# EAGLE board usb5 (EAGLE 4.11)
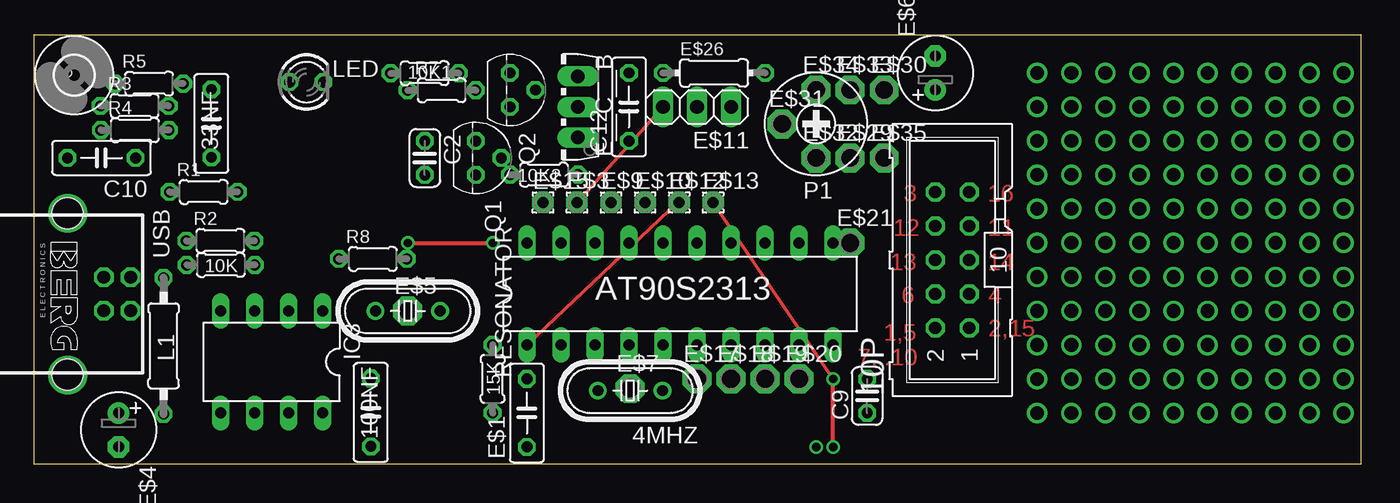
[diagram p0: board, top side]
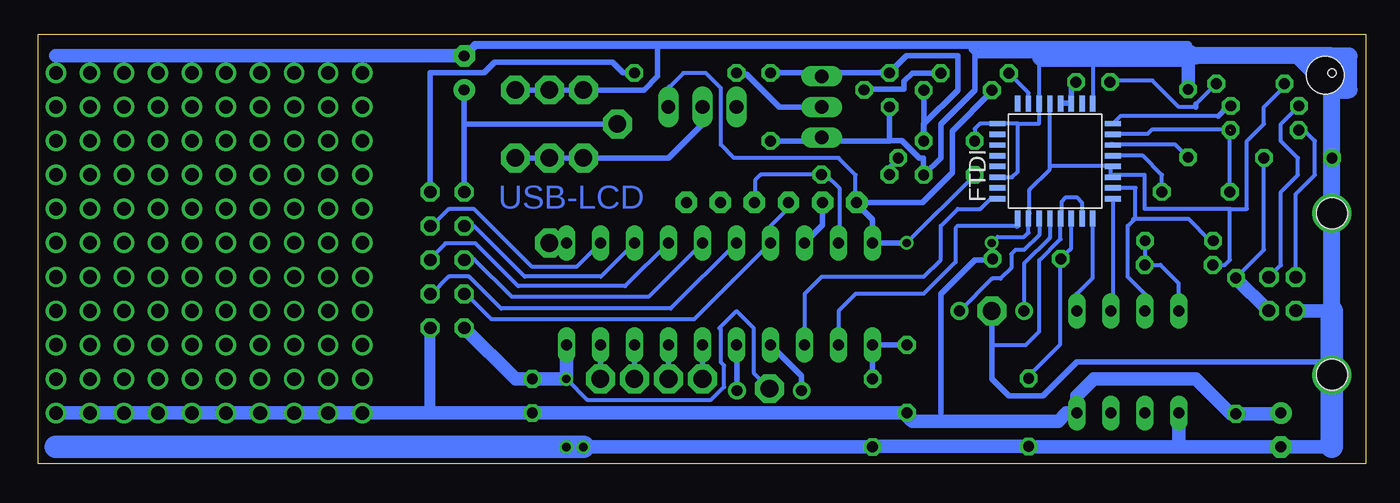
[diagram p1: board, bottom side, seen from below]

Size 99.13 x 32.09 mm. Coordinates in mm from the lower left corner, seen from the top.
Outline: 99.13,32.09 99.13,0 0,0 0,32.08
Outline: 0,32.09 0,32.08
Outline: 0,32.08 99.12,32.08
Copper layers (1*16): Top 0.035mm / dielectric 1.5mm / Bottom 0.035mm
Design rules "default": minimum track width 10mil, minimum drill 24mil, track to track 8mil, track to pad 8mil, pad to pad 8mil, via to via 8mil, smd to smd 8mil, copper to edge 40mil, drill to drill 8mil, minimum pad ring 10mil, minimum via ring 8mil, stop-mask expansion 4mil, vias tented up to drill 0mil, thermal gap 10mil
Holes 0.61 mm at 2.54,29.21

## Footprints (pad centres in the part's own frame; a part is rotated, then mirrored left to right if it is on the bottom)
HC49/S = drill 0.813 round: 1 -2.413,0; 2 2.413,0
0204/5 = drill 0.813 octagon: 1 -2.54,0; 2 2.54,0
ML10 = drill 0.914 octagon: 1 -5.08,-1.27; 2 -5.08,1.27; 3 -2.54,-1.27; 4 -2.54,1.27; 5 0,-1.27; 6 0,1.27; 7 2.54,-1.27; 8 2.54,1.27; 9 5.08,-1.27; 10 5.08,1.27
C050-025X075 = drill 0.813 octagon: 1 -2.54,0; 2 2.54,0
DIL20 = drill 0.813 long: 1 -11.43,-3.81; 2 -8.89,-3.81; 3 -6.35,-3.81; 4 -3.81,-3.81; 5 -1.27,-3.81; 6 1.27,-3.81; 7 3.81,-3.81; 8 6.35,-3.81; 9 8.89,-3.81; 10 11.43,-3.81; 11 11.43,3.81; 12 8.89,3.81; 13 6.35,3.81; 14 3.81,3.81; 15 1.27,3.81; 16 -1.27,3.81; 17 -3.81,3.81; 18 -6.35,3.81; 19 -8.89,3.81; 20 -11.43,3.81
C025-024X044 = drill 0.813 octagon: 1 -1.27,0; 2 1.27,0
2,8 = hole 2.8: 0,0
1,6/0,8 = drill 0.813 pad 1.6 octagon: 1 0,0
E2,5-6 = drill 0.813 pad 1.6 round: + -1.27,0 | drill 0.813 pad 1.6 octagon: - 1.27,0
P1-13 = drill 1.321 pad 2.159 octagon: 1 0,0
1X03 = drill 1.016 long: 1 -2.54,0; 2 0,0; 3 2.54,0
0204/7 = drill 0.813 octagon: 1 -3.81,0; 2 3.81,0
TO126AV = drill 1.016 long: B 2.286,-1.27; C 0,-1.27; E -2.286,-1.27
LQFP32 = smd 0.4 x 1.2: 1 -2.8,-4.3; 2 -2,-4.3; 3 -1.2,-4.3; 4 -0.4,-4.3; 5 0.4,-4.3; 6 1.2,-4.3; 7 2,-4.3; 8 2.8,-4.3; 17 2.8,4.3; 18 2,4.3; 19 1.2,4.3; 20 0.4,4.3; 21 -0.4,4.3; 22 -1.2,4.3; 23 -2,4.3; 24 -2.8,4.3 | smd 1.2 x 0.4: 9 4.3,-2.8; 10 4.3,-2; 11 4.3,-1.2; 12 4.3,-0.4; 13 4.3,0.4; 14 4.3,1.2; 15 4.3,2; 16 4.3,2.8; 25 -4.3,2.8; 26 -4.3,2; 27 -4.3,1.2; 28 -4.3,0.4; 29 -4.3,-0.4; 30 -4.3,-1.2; 31 -4.3,-2; 32 -4.3,-2.8
DIL08 = drill 0.813 long: 1 -3.81,-3.81; 2 -1.27,-3.81; 3 1.27,-3.81; 4 3.81,-3.81; 5 3.81,3.81; 6 1.27,3.81; 7 -1.27,3.81; 8 -3.81,3.81
0207/10 = drill 0.813 octagon: 1 -5.08,0; 2 5.08,0
LED3MM = drill 0.813 octagon: A -1.27,0; K 1.27,0
RTRIM3339P = drill 0.61 round: 1 -2.54,0; 2 0,-2.54; 3 2.54,0
TO92 = drill 0.813 octagon: 1 1.27,0; 2 0,1.905; 3 -1.27,0
PN61729 = drill 0.95 octagon: 1 1.25,4.71; 2 -1.25,4.71; 3 -1.25,2.71; 4 1.25,2.71 | hole 2.3: -6.02,0; 6.02,0

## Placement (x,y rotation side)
4MHZ  4Mhz  [HC49/S]  44.54,5.48 180 top
10K  15k  [0204/5]  13.98,14.87 180 top
10K1  10k  [0204/5]  29.2,29.19 0 top
10K2  10k  [0204/5]  38.11,21.61 180 top
10P  LCD  [ML10]  68.58,15.24 90 top
15K  15k  [0204/5]  34.27,6.36 270 top
33NF  [C050-025X075]  13.28,25.44 90 top
100NF  [C050-025X075]  25.18,3.85 90 top
AT90S2313  AT90S2313  [DIL20]  48.26,12.7 0 top
C2  100nf  [C025-024X044]  29.21,22.86 270 top
C9  100nf  [C025-024X044]  62.23,5.08 90 top
C10  10nF  [C050-025X075]  5.08,22.86 180 top
C12  100nF  [C050-025X075]  44.45,26.67 90 top
E$1  100nF  [C050-025X075]  36.83,3.81 90 top
E$2  [2,8]  3.04,29.04 0 top
E$3  [1,6/0,8]  40.57,19.53 0 top
E$4  10uf  [E2,5-6]  6.35,2.54 270 top
E$5  [P1-13]  27.94,11.43 0 top
E$6  10uF  [E2,5-6]  67.31,29.21 90 top
E$7  [P1-13]  44.53,5.63 0 top
E$9  [1,6/0,8]  43.11,19.53 0 top
E$10  [1,6/0,8]  45.65,19.53 0 top
E$11  [1X03]  49.53,26.67 180 top
E$12  [1,6/0,8]  48.19,19.53 0 top
E$13  [1,6/0,8]  50.73,19.53 0 top
E$15  [1,6/0,8]  38.03,19.53 0 top
E$17  [P1-13]  49.53,6.35 0 top
E$18  [P1-13]  52.07,6.35 0 top
E$19  [P1-13]  54.61,6.35 0 top
E$20  [P1-13]  57.15,6.35 0 top
E$21  [P1-13]  60.96,16.51 0 top
E$26  rx  [0204/7]  50.8,29.21 0 top
E$29  [P1-13]  60.96,22.86 0 top
E$30  [P1-13]  63.5,27.94 0 top
E$31  [P1-13]  55.88,25.4 0 top
E$32  [P1-13]  58.42,22.86 0 top
E$33  [P1-13]  60.96,27.94 0 top
E$34  [P1-13]  58.42,27.94 0 top
E$35  [P1-13]  63.5,22.86 0 top
E__C__B  BD139  [TO126AV]  39.37,26.67 90 top
FTDI  FT232BM  [LQFP32]  23.2,22.62 90 bottom
IC3  93C48  [DIL08]  17.78,7.62 180 top
L1  [0207/10]  9.71,8.82 270 top
LED  [LED3MM]  20.38,28.53 0 top
P1  10K  [RTRIM3339P]  58.42,25.4 270 top
Q1  [TO92]  33.02,22.86 270 top
Q2  BC547  [TO92]  35.56,27.94 270 top
R1  1k5  [0204/5]  12.7,20.32 0 top
R2  2k2  [0204/5]  13.95,16.67 0 top
R3  27  [0204/5]  7.55,26.75 0 top
R4  27  [0204/5]  7.57,24.94 0 top
R5  220  [0204/5]  8.63,28.41 0 top
R7  1k  [0204/5]  30.47,27.92 0 top
R8  470  [0204/5]  25.33,15.32 0 top
RESONATOR  6Mhz  [HC49/S]  27.94,11.43 180 top
USB  [PN61729]  2.54,12.7 270 top

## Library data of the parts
4MHZ RESONATOR = crystal
10K 10K1 10K2 15K 33NF 100NF C2 C9 C10 C12 E$1 E$4 E$6 E$26 L1 P1 R1-R5 R7 R8 = rcl
10P = con-harting-ml
AT90S2313 = atmel
E$2 = holes
E$3 E$9 E$10 E$12 E$13 E$15 = wirepad
E$5 E$7 E$17-E$21 E$29-E$35 = testpad
E$11 = pinhead
E__C__B = transistor-power
FTDI = ftdi_FT2XXBM
IC3 = ic-package
LED = led
Q1 Q2 = transistor
USB = con-berg

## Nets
GND: 10P.2 33NF.2 100NF.1 AT90S2313.10 C9.2 E$1.1 E$4.- E$5.1 E$6.- E$7.1 E$13.1 E$30.1 E$33.1 FTDI.9 FTDI.29 FTDI.31 IC3.5 P1.1 USB.4
S$1: R3.1 USB.2
S$3: FTDI.28 RESONATOR.2
S$6: 100NF.2 FTDI.30 R8.1
S$7: R4.1 USB.3
S$8: FTDI.8 R3.2
S$9: FTDI.7 R1.1 R4.2
S$11: 10K.1 IC3.4 R2.2
S$12: FTDI.27
S$13: FTDI.1 IC3.2
S$14: FTDI.2 IC3.3 R2.1
S$15: FTDI.5 R1.2
S$16: 33NF.1 FTDI.6
S$17: LED.A R5.2
S$18: 15K.1 AT90S2313.1 E$1.2 E$12.1
S$19: RESONATOR.1
S$20: C10.1 L1.1 USB.1
S$21: C2.1 FTDI.17
S$22: AT90S2313.3 FTDI.24
S$23: E$26.1 E__C__B.C
S$24: AT90S2313.2 FTDI.25
S$25: 4MHZ.2 AT90S2313.4
S$26: 4MHZ.1 AT90S2313.5
S$27: AT90S2313.6 E$17.1
S$28: AT90S2313.7 E$18.1
S$29: AT90S2313.8 E$19.1
S$30: AT90S2313.9 E$20.1
S$31: AT90S2313.11 E$21.1
S$32: 10K1.1 FTDI.15
S$33: C12.2 E__C__B.B Q1.3 Q2.3 R7.2
S$34: 10K1.2 Q2.2
S$36: FTDI.14 FTDI.22
S$37: 10K2.1 AT90S2313.19 E$10.1
S$38: 10K2.2 Q1.2
S$39: 10P.9 E$26.2
S$40: AT90S2313.18 E$3.1 E$11.3
S$41: E$11.2 E$29.1 E$35.1 P1.3
S$42: 10P.10 E$6.+ P1.2
S$43: 10P.7 AT90S2313.12
S$44: 10P.8 AT90S2313.13
S$45: 10P.5 AT90S2313.14
S$46: 10P.6 AT90S2313.15
S$47: 10P.3 AT90S2313.16
S$48: 10P.4 AT90S2313.17 E$9.1
S$49: C12.1 E__C__B.E Q1.1 Q2.1
S$150: FTDI.11 FTDI.12 LED.K
S$153: AT90S2313.20 C2.2 E$11.1 E$15.1 FTDI.13 FTDI.26 R7.1 R8.2
S$154: 10K.2 FTDI.3 FTDI.4 R5.1
S$158: FTDI.32 IC3.1
VCC: 10P.1 15K.2 E$4.+ IC3.8 L1.2

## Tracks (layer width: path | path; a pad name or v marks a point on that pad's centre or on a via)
GND  (via drill 0.61)
  Top 0.254: v59.69,6.35 E$13.1
  Top 0.305: v59.69,1.27 v59.69,6.35
  Bottom 0.254: 23.92,30.48 23.92,30.16 2.56,30.16 2.54,11.43 USB.4
  Bottom 0.305: E$7.1 45.72,6.82 45.72,10.16 46.99,11.43 48.26,10.16 48.16,10.06 48.16,7.6 47.92,7.36 47.92,5.76 48.88,4.8 58.14,4.8 v59.69,6.35 | 20.4,30.4 FTDI.9 | FTDI.31 21.2,19.52 21.6,19.92 22.4,19.92 22.72,19.6 22.72,18.24 FTDI.29 22.8,16.8 24.4,15.2 24.4,9.89 25.4,8.89 27.94,8.89
  Bottom 0.406: P1.1 E$33.1 E$30.1 53.9,27.94 52.88,28.96 52.88,31.28 | 20.32,30.48 20.4,30.4 | USB.4 5.23,11.43 2.54,11.43 | E$5.1 27.94,8.89 27.94,6.35 26.67,5.08 24.13,5.08 21.59,7.62 2.54,7.62
  Bottom 0.425: 100NF.1 25.36,1.31 25.4,1.27
  Bottom 0.61: E$6.- 66.51,31.28 52.88,31.28 13.28,31.28 13.28,28 | 13.28,28 13.2,28 | 33NF.2 13.28,28
  Bottom 1: E$1.1 v58.42,1.27
  Bottom 1.016: E$6.- 97.79,30.48 | 10P.2 63.5,6.35 C9.2 v59.69,6.35 AT90S2313.10 | 13.28,30.48 33NF.2 | E$1.1 36.83,1.31 25.4,1.31 | 25.4,1.31 100NF.1 | 25.4,1.31 25.4,1.27 13.97,1.27 | 13.97,1.27 IC3.5 | 13.97,1.27 E$4.- 2.54,1.27 | 2.54,11.43 5.08,11.43
  Bottom 1.27: 5.08,30.48 12.7,30.48 | 3.81,29.21 5.08,30.48 | 2.54,30.48 5.08,30.48 | 2.54,30.48 1.27,30.48 1.27,27.94 2.54,27.94 | 2.54,30.48 3.81,29.21 | 2.54,27.94 2.54,30.48 | 2.54,27.94 3.81,29.21 | 2.54,11.43 2.54,27.94
  Bottom 1.676: 97.79,1.27 v59.69,1.27 v58.42,1.27 | 13.28,30.48 20.32,30.48 23.92,30.48 24.13,30.48 | 2.54,1.27 2.54,7.62 2.54,11.43
S$1
  Bottom 0.305: USB.2 6.35,14.85 6.35,20.32 5.08,21.59 5.08,22.86 6.35,24.13 6.35,25.4 5.08,26.67
  Bottom 0.406: 5.08,26.67 5.08,26.68 R3.1
S$2  (via drill 0.61)
  other vias: 25.2,1.28
S$3
  Bottom 0.305: FTDI.28 23.6,16.88 25.52,14.96 25.52,11.52 25.6,11.44 25.59,11.43 RESONATOR.2
S$4  (via drill 1.93)
  other vias: 2.56,6.64
S$5  (via drill 1.93)
  other vias: 2.56,18.72
S$6
  Bottom 0.305: 22.8,15.3 arc-45 R8.1 arc45 22.8,15.3 | 22.8,15.3 22.86,15.24 | FTDI.30 22,16.23 arc45 22.09,16.01 22.86,15.24 | 22.86,15.24 22.86,8.89 25.36,6.39 | 25.4,6.35 25.36,6.39 | 25.36,6.39 100NF.2
S$7
  Bottom 0.305: USB.3 5.25,20.15 3.81,21.59 3.81,24.13 5.08,25.4
  Bottom 0.406: 5.08,25.4 R4.1
S$8
  Bottom 0.305: FTDI.8 18.32,26 11.04,26
  Bottom 0.406: 10.06,26.72 10,26.72 | R3.2 10.06,26.72 | 11.04,26 10.32,26.72 10.06,26.72
S$9  (1 unrouted)
  Bottom 0.305: R1.1 10.16,24.96 16,24.96 16.32,24.64 18.92,24.64
  Bottom 0.406: 19.04,24.64 18.92,24.64 FTDI.7
S$11
  Bottom 0.305: 16.52,14.84 16.56,14.8 | 16.52,14.84 10K.1 15.35,14.87 14,13.52 14,11.46 IC3.4 | R2.2 16.49,14.87 16.52,14.84
S$12
  Bottom 0.305: FTDI.27 24.4,18.16
S$13
  Bottom 0.305: FTDI.1 18.9,11.58 IC3.2
S$14
  Bottom 0.305: 17.2,18.32 17.36,18.32 17.36,18.2 17.78,17.78 17.78,13.97 16.51,12.7 IC3.3 | 17.2,18.32 13.28,18.32 11.68,16.72 11.36,16.72 R2.1 | FTDI.2 17.2,20.62 17.2,18.32
S$15
  Bottom 0.305: FTDI.5 16.67,23.02 15.24,21.59 R1.2
S$16
  Bottom 0.305: 33NF.1 14.22,23.84 18.92,23.84
  Bottom 0.406: 19.04,23.84 18.92,23.84 FTDI.6
S$17
  Bottom 0.305: R5.2 12.7,26.88 | 12.7,26.67 13.97,26.67 15.94,28.64 19.04,28.64
  Bottom 0.406: 12.7,26.88 12.7,26.67 | 19.04,28.64 19.04,28.6 LED.A
S$18
  Top 0.254: E$12.1 48.16,19.6 AT90S2313.1
  Bottom 0.406: 15K.1 AT90S2313.1 E$1.2
S$19
  Bottom 0.305: 24.4,18 24.4,17.12 25.52,16 26.16,16 26.48,15.68 26.48,14.64 27.28,13.84 27.92,13.84 30.33,11.43 RESONATOR.1
S$20
  Bottom 0.305: L1.1 7.62,15.99 C10.1
  Bottom 1.016: L1.1 9.71,13.87 7.29,11.45 USB.1
S$21
  Bottom 0.305: FTDI.17 28.82,25.42 29.2,25.04 29.2,24 29.21,24.01 C2.1
S$22
  Bottom 0.305: AT90S2313.3 41.91,12.7 40.64,13.97 33.02,13.97 31.75,15.24 31.75,17.78 30.48,19.05 28.79,19.05 28,19.84 27.98,19.82 FTDI.24
S$23
  Bottom 0.406: E__C__B.C 43.79,26.67 46.24,29.12 46.72,29.12 46.81,29.21 E$26.1
S$24
  Bottom 0.305: AT90S2313.2 39.37,11.43 38.1,12.7 33.02,12.7 30.64,15.08 30.64,17.62 30.48,17.78 26.06,17.78 | FTDI.25 26,17.84
  Bottom 0.406: 26,17.84 26.06,17.78
S$25
  Bottom 0.406: 4MHZ.2 42.13,6.57 AT90S2313.4
S$26
  Bottom 0.406: 4MHZ.1 46.95,8.85 AT90S2313.5
S$27
  Bottom 0.406: E$17.1 AT90S2313.6
S$28
  Bottom 0.406: E$18.1 AT90S2313.7
S$29
  Bottom 0.406: E$19.1 AT90S2313.8
S$30
  Bottom 0.406: E$20.1 AT90S2313.9
S$31
  Bottom 0.305: AT90S2313.11 E$21.1
S$32
  Bottom 0.305: 10K1.1 25.2,27.73 FTDI.15
S$33
  Bottom 0.406: 40.64,29.21 C12.2 | R7.2 Q1.3
  Bottom 0.425: E__C__B.B 40.64,29.21 Q2.3 34.29,30.48 30.48,30.48 30.48,27.94 33.02,25.4 Q1.3
S$34
  Bottom 0.425: 10K1.2 33.87,29.19 34.48,28.58 34.48,28 37.44,28 37.44,27.96 Q2.2
S$35  (via drill 1.02)
  other vias: 85.09,26.67
S$36
  Bottom 0.305: 24.4,29.84 FTDI.14 24.4,25.44 26,25.44 | 26,25.44 27.36,25.44 | 26,25.44 26,21.84 26.42,21.42 FTDI.22
S$37
  Bottom 0.305: 39.28,16.6 39.28,20.56 40.31,21.59 | 10K2.1 45.19,21.61 45.6,21.2 45.6,19.52
  Bottom 0.406: AT90S2313.19 39.28,16.6 | 10K2.1 40.64,21.59 40.31,21.59 | 45.6,19.52 45.61,19.53 E$10.1
S$38
  Bottom 0.406: Q1.2 34.92,22.84 34.88,22.8 35.57,22.11 10K2.2
S$39
  Bottom 0.406: E$26.2 55.45,29.21 56.24,30 65.04,30 65.83,29.21 69.85,29.21 10P.9
S$40
  Top 0.254: E$3.1 E$11.3
  Bottom 0.406: E$3.1 40.56,19.6 | E$3.1 | AT90S2313.18 40.56,17.86 E$3.1
S$41
  Bottom 0.406: E$11.2 49.53,25.4 52.07,22.86 P1.3 E$29.1 E$35.1
S$42
  Bottom 0.406: P1.2 67.31,25.4 E$6.+ 10P.10
S$43
  Bottom 0.305: AT90S2313.12 58.94,14.72 62.24,14.72 66.56,19.04 68.48,19.04 69.74,17.78 10P.7
S$44
  Bottom 0.305: AT90S2313.13 57.12,14 62.8,14 66.56,17.76 67.29,17.76 10P.8
S$45
  Bottom 0.305: AT90S2313.14 55.3,13.28 63.28,13.28 66.48,16.48 68.72,16.48 69.84,15.36 10P.5 | 10P.5 69.84,15.12 | 10P.5
S$46
  Bottom 0.305: AT90S2313.15 53.56,12.48 63.76,12.48 66.56,15.28 67.35,15.28 | 67.35,15.28 67.36,15.28 | 67.35,15.28 10P.6
S$47
  Bottom 0.305: AT90S2313.16 51.9,11.6 64.56,11.6 66.96,14 68.48,14 69.84,12.64 69.91,12.64 | 69.91,12.64 69.92,12.64 | 69.91,12.64 10P.3
S$48
  Bottom 0.305: 43.12,19.11 44.45,17.78 AT90S2313.17 50.16,10.8 65.28,10.8 67.2,12.72 67.29,12.72 10P.4
  Bottom 0.406: E$9.1 43.12,19.11
S$49
  Bottom 0.406: 35.6,24.13 35.6,24.16 34.64,24.16 33.34,22.86 33.02,22.86 Q1.1
  Bottom 0.425: 40.39,24.13 C12.1 | 40.39,24.13 E__C__B.E | Q2.1 35.56,24.13 35.6,24.13 40.39,24.13 | 25.2,30.96 28.72,30.96 29.2,30.48 29.21,30.48 29.21,27.94 31.75,25.4 31.75,22.86 Q1.1
S$50  (via drill 1.02)
  other vias: 74.93,29.21
S$51  (via drill 1.02)
  other vias: 77.47,29.21
S$52  (via drill 1.02)
  other vias: 80.01,29.21
S$53  (via drill 1.02)
  other vias: 82.55,29.21
S$54  (via drill 1.02)
  other vias: 85.09,29.21
S$55  (via drill 1.02)
  other vias: 87.63,29.21
S$56  (via drill 1.02)
  other vias: 90.17,29.21
S$57  (via drill 1.02)
  other vias: 92.71,29.21
S$58  (via drill 1.02)
  other vias: 95.25,29.21
S$59  (via drill 1.02)
  other vias: 97.79,29.21
S$60  (via drill 1.02)
  other vias: 74.93,26.67
S$61  (via drill 1.02)
  other vias: 77.47,26.67
S$62  (via drill 1.02)
  other vias: 80.01,26.67
S$63  (via drill 1.02)
  other vias: 82.55,26.67
S$64  (via drill 1.02)
  other vias: 87.63,26.67
S$65  (via drill 1.02)
  other vias: 90.17,26.67
S$66  (via drill 1.02)
  other vias: 92.71,26.67
S$67  (via drill 1.02)
  other vias: 95.25,26.67
S$68  (via drill 1.02)
  other vias: 97.79,26.67
S$69  (via drill 1.02)
  other vias: 97.79,24.13
S$70  (via drill 1.02)
  other vias: 97.79,21.59
S$71  (via drill 1.02)
  other vias: 97.79,19.05
S$72  (via drill 1.02)
  other vias: 97.79,16.51
S$73  (via drill 1.02)
  other vias: 97.79,13.97
S$74  (via drill 1.02)
  other vias: 97.79,11.43
S$75  (via drill 1.02)
  other vias: 97.79,8.89
S$76  (via drill 1.02)
  other vias: 97.79,6.35
S$77  (via drill 1.02)
  other vias: 95.25,6.35
S$78  (via drill 1.02)
  other vias: 92.71,6.35
S$79  (via drill 1.02)
  other vias: 90.17,6.35
S$80  (via drill 1.02)
  other vias: 74.93,24.13
S$81  (via drill 1.02)
  other vias: 74.93,21.59
S$82  (via drill 1.02)
  other vias: 74.93,19.05
S$83  (via drill 1.02)
  other vias: 74.93,16.51
S$84  (via drill 1.02)
  other vias: 74.93,13.97
S$85  (via drill 1.02)
  other vias: 77.47,24.13
S$86  (via drill 1.02)
  other vias: 80.01,21.59
S$87  (via drill 1.02)
  other vias: 77.47,21.59
S$88  (via drill 1.02)
  other vias: 80.01,24.13
S$89  (via drill 1.02)
  other vias: 82.55,24.13
S$90  (via drill 1.02)
  other vias: 82.55,21.59
S$91  (via drill 1.02)
  other vias: 85.09,21.59
S$92  (via drill 1.02)
  other vias: 85.09,24.13
S$93  (via drill 1.02)
  other vias: 87.63,24.13
S$94  (via drill 1.02)
  other vias: 90.17,24.13
S$95  (via drill 1.02)
  other vias: 92.71,24.13
S$96  (via drill 1.02)
  other vias: 95.25,24.13
S$97  (via drill 1.02)
  other vias: 95.25,21.59
S$98  (via drill 1.02)
  other vias: 92.71,21.59
S$99  (via drill 1.02)
  other vias: 90.17,21.59
S$100  (via drill 1.02)
  other vias: 87.63,21.59
S$101  (via drill 1.02)
  other vias: 85.09,19.05
S$102  (via drill 1.02)
  other vias: 82.55,19.05
S$103  (via drill 1.02)
  other vias: 80.01,19.05
S$104  (via drill 1.02)
  other vias: 77.47,19.05
S$105  (via drill 1.02)
  other vias: 77.47,16.51
S$106  (via drill 1.02)
  other vias: 80.01,16.51
S$107  (via drill 1.02)
  other vias: 82.55,16.51
S$108  (via drill 1.02)
  other vias: 85.09,16.51
S$109  (via drill 1.02)
  other vias: 87.63,16.51
S$110  (via drill 1.02)
  other vias: 87.63,19.05
S$111  (via drill 1.02)
  other vias: 90.17,19.05
S$112  (via drill 1.02)
  other vias: 90.17,16.51
S$113  (via drill 1.02)
  other vias: 92.71,16.51
S$114  (via drill 1.02)
  other vias: 92.71,19.05
S$115  (via drill 1.02)
  other vias: 95.25,19.05
S$116  (via drill 1.02)
  other vias: 95.25,16.51
S$117  (via drill 1.02)
  other vias: 95.25,13.97
S$118  (via drill 1.02)
  other vias: 95.25,11.43
S$119  (via drill 1.02)
  other vias: 95.25,8.89
S$120  (via drill 1.02)
  other vias: 92.71,8.89
S$121  (via drill 1.02)
  other vias: 92.71,11.43
S$122  (via drill 1.02)
  other vias: 92.71,13.97
S$123  (via drill 1.02)
  other vias: 90.17,13.97
S$124  (via drill 1.02)
  other vias: 87.63,13.97
S$125  (via drill 1.02)
  other vias: 85.09,13.97
S$126  (via drill 1.02)
  other vias: 82.55,13.97
S$127  (via drill 1.02)
  other vias: 80.01,13.97
S$128  (via drill 1.02)
  other vias: 77.47,13.97
S$129  (via drill 1.02)
  other vias: 74.93,11.43
S$130  (via drill 1.02)
  other vias: 74.93,8.89
S$131  (via drill 1.02)
  other vias: 74.93,6.35
S$132  (via drill 1.02)
  other vias: 77.47,6.35
S$133  (via drill 1.02)
  other vias: 80.01,6.35
S$134  (via drill 1.02)
  other vias: 82.55,6.35
S$135  (via drill 1.02)
  other vias: 85.09,6.35
S$136  (via drill 1.02)
  other vias: 87.63,6.35
S$137  (via drill 1.02)
  other vias: 87.63,8.89
S$138  (via drill 1.02)
  other vias: 90.17,8.89
S$139  (via drill 1.02)
  other vias: 90.17,11.43
S$140  (via drill 1.02)
  other vias: 87.63,11.43
S$141  (via drill 1.02)
  other vias: 85.09,11.43
S$142  (via drill 1.02)
  other vias: 82.55,11.43
S$143  (via drill 1.02)
  other vias: 80.01,11.43
S$144  (via drill 1.02)
  other vias: 77.47,11.43
S$145  (via drill 1.02)
  other vias: 77.47,8.89
S$146  (via drill 1.02)
  other vias: 80.01,8.89
S$147  (via drill 1.02)
  other vias: 82.55,8.89
S$148  (via drill 1.02)
  other vias: 85.09,8.89
S$149
  Bottom 0.305: 69.84,20.24 69.85,20.25
S$150
  Bottom 0.406: LED.K 22,28.18 FTDI.11 22.04,26.96 22.76,26.96 FTDI.12
S$151
  Bottom 0.425: 25.28,30.72 29.04,30.72 29.28,30.96 29.44,30.96 28.96,30.48 25.04,30.48
S$152
  Bottom 0.406: 25.12,30.88 24.72,30.88
S$153  (via drill 0.61)
  Top 0.305: v27.94,16.51 v34.29,16.51
  Bottom 0.305: 52,28.16 50.96,29.2 49.28,29.2 48.16,28.08 48.16,23.84 47.18,22.86 39.37,22.86 38.1,21.59 38.1,19.46 | 23.6,27.2 FTDI.13 23.6,22 25.12,20.48 25.12,18.72 25.2,18.64 FTDI.26 25.2,17.28 25.52,16.96 27.49,16.96 v27.94,16.51 | 34.32,16.48 v34.29,16.51 C2.2 | 27.88,15.3 arc-45 R8.2 27.94,15.24 27.88,15.3
  Bottom 0.406: E$11.1 52.04,26.64 52,26.64 52,28.16 | R7.1 27.93,27.85 27.92,27.84 30.88,24.88 30.88,21.76 33.11,19.53 E$15.1 | 38.1,19.05 38.1,19.46 E$15.1 | E$15.1 38.03,19.47 36.83,18.27 AT90S2313.20 v34.29,16.51 | v27.94,16.51 27.87,16.44 R8.2 | 27.94,15.24 29.21,15.24 31.75,12.7 31.75,3.81
S$154
  Bottom 0.305: 23.52,22.24 23.51,22.24 19.04,22.24 | FTDI.4 19.02,22.22 19.04,22.24 | R5.1 6.09,28.2 7.62,26.67 7.62,25.4 8.89,24.13 8.89,19.05 10.16,19.05 | 18.9,21.44 FTDI.3 19.05,21.42 19.05,21.59 | 19.04,22.24 19.05,22.23 19.05,21.59 | 19.05,21.59 16.51,21.59 16.51,19.05 10.16,19.05 | 10.16,19.05 10.16,15.24 10.53,14.87 10K.2
  Bottom 0.406: 18.96,22.24 18.9,22.24 FTDI.4
S$155  (via drill 1.02)
  other vias: 74.93,3.81
S$156  (via drill 1.02)
  other vias: 77.47,3.81
S$157  (via drill 1.02)
  other vias: 80.01,3.81
S$158
  Bottom 0.305: FTDI.32 20.4,13.89 21.59,12.7 IC3.1
S$159  (via drill 1.02)
  other vias: 82.55,3.81
S$160  (via drill 1.02)
  other vias: 85.09,3.81
S$161  (via drill 1.02)
  other vias: 97.79,3.81
S$162  (via drill 1.02)
  other vias: 95.25,3.81
S$163  (via drill 1.02)
  other vias: 92.71,3.81
S$164  (via drill 1.02)
  other vias: 90.17,3.81
S$165  (via drill 1.02)
  other vias: 87.63,3.81
VCC
  Bottom 0.305: 34.29,3.81 34.29,3.81 arc45 15K.2
  Bottom 0.425: 97.79,3.81 69.85,3.81 60.96,3.81 48.26,3.81
  Bottom 0.813: 10P.1 69.85,3.81 69.85,3.82
  Bottom 1: 97.79,3.81 97.78,3.82 69.85,3.82 60.96,3.82 15K.2
  Bottom 1.016: 34.29,3.74 34.29,3.81 34.29,3.82 15K.2 34.27,3.73 34.32,3.68 33.84,3.2 22.96,3.2 22.35,3.81 IC3.8 21.59,5.08 20.32,6.35 12.7,6.35 10.09,3.74 L1.2 6.35,3.74 E$4.+ | 60.96,3.82 60.96,3.81

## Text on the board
Top: 3 | 16 | 12 | 11 | 13 | 14 | 6 | 4 | 2,15 | 1,5 | 7...10
Bottom: USB-LCD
